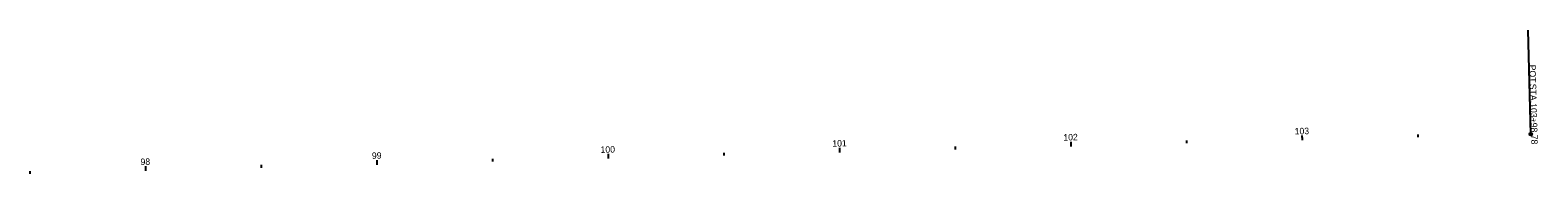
# Model space of a CAD drawing. Extents: x 2402033 to 2407435, y 498456 to 498900.
# Drawn here: x 2406783 to 2407435, y 498766 to 498828 of the extents above; entities that cross this region are included whole.
import ezdxf

# ---------------------------------------------------------------- set-up
doc = ezdxf.new("R2010")
doc.units = 0
for name, color, linetype in [('DR_P_Ditch', 7, 'Continuous'), ('DV_X_Property_Line', 7, 'Continuous'), ('RW_P_Esmt_CH', 7, 'Continuous'), ('RW_P_Esmt_SH', 7, 'Continuous'), ('RW_X_Esmt_SH', 7, 'Continuous'), ('RW_X_Parent_Tract_Area', 7, 'Continuous')]:
    doc.layers.add(name, color=color, linetype=linetype)

msp = doc.modelspace()

# ---------------------------------------------------------------- linework, layer by layer
at = {"layer": 'DR_P_Ditch'}
msp.add_line((2407033.06, 498772.48), (2407033.01, 498774.48), dxfattribs=at)
at = {"layer": 'DV_X_Property_Line'}
msp.add_line((2407431.7, 498783.04), (2407430.51, 498828.02), dxfattribs=at)
msp.add_circle((2407431.7, 498783.04), 0.6, dxfattribs=at)
at = {"layer": 'RW_P_Esmt_CH'}
for p, q in [((2407232.99, 498777.77), (2407232.96, 498778.97)), ((2407332.96, 498780.42), (2407332.92, 498781.62)), ((2407033.06, 498772.48), (2407033.01, 498774.48)), ((2407133.03, 498775.13), (2407132.99, 498776.33)), ((2406833.13, 498767.19), (2406833.1, 498768.39)), ((2406933.1, 498769.83), (2406933.06, 498771.03))]:
    msp.add_line(p, q, dxfattribs=at)
at = {"layer": 'RW_P_Esmt_SH'}
msp.add_line((2407431.7, 498783.04), (2407430.51, 498828.02), dxfattribs=at)
msp.add_circle((2407431.7, 498783.04), 0.6, dxfattribs=at)
at = {"layer": 'RW_X_Esmt_SH'}
for p, q in [((2407232.99, 498777.77), (2407232.94, 498779.77)), ((2407282.97, 498779.1), (2407282.94, 498780.3)), ((2407332.96, 498780.42), (2407332.9, 498782.42)), ((2407382.94, 498781.74), (2407382.91, 498782.94)), ((2406933.1, 498769.83), (2406933.04, 498771.83)), ((2406983.08, 498771.16), (2406983.05, 498772.36)), ((2407033.06, 498772.48), (2407033.01, 498774.48)), ((2407083.04, 498773.8), (2407083.01, 498775)), ((2407133.03, 498775.13), (2407132.97, 498777.13)), ((2407183.01, 498776.45), (2407182.98, 498777.65)), ((2406783.15, 498765.86), (2406783.12, 498767.06)), ((2406833.13, 498767.19), (2406833.08, 498769.19)), ((2406883.11, 498768.51), (2406883.08, 498769.71))]:
    msp.add_line(p, q, dxfattribs=at)
at = {"layer": 'RW_X_Parent_Tract_Area'}
msp.add_line((2407431.7, 498783.04), (2407430.51, 498828.02), dxfattribs=at)
msp.add_circle((2407431.7, 498783.04), 0.6, dxfattribs=at)

# ---------------------------------------------------------------- texts
at = {"layer": 'DR_P_Ditch'}
msp.add_text('100', height=2.8, rotation=1.5166, dxfattribs=at).set_placement((2407029.65, 498774.93))
at = {"layer": 'DV_X_Property_Line'}
for s, p in [('POT', (2407430.94, 498813.03)), (' STA. ', (2407431.14, 498805.83)), ('103+98.78', (2407431.39, 498796.38))]:
    msp.add_text(s, height=2.8, rotation=271.5166, dxfattribs=at).set_placement(p)
at = {"layer": 'RW_P_Esmt_CH'}
msp.add_text('100', height=2.8, rotation=1.5166, dxfattribs=at).set_placement((2407029.65, 498774.93))
at = {"layer": 'RW_P_Esmt_SH'}
for s, p in [('POT', (2407430.94, 498813.03)), (' STA. ', (2407431.14, 498805.83)), ('103+98.78', (2407431.39, 498796.38))]:
    msp.add_text(s, height=2.8, rotation=271.5166, dxfattribs=at).set_placement(p)
at = {"layer": 'RW_X_Esmt_SH'}
for s, p in [('103', (2407329.62, 498782.88)), ('100', (2407029.65, 498774.93)), ('101', (2407129.81, 498777.59)), ('102', (2407229.65, 498780.23)), ('98', (2406830.85, 498769.67)), ('99', (2406930.83, 498772.32))]:
    msp.add_text(s, height=2.8, rotation=1.5166, dxfattribs=at).set_placement(p)
at = {"layer": 'RW_X_Parent_Tract_Area'}
for s, p in [('POT', (2407430.94, 498813.03)), (' STA. ', (2407431.14, 498805.83)), ('103+98.78', (2407431.39, 498796.38))]:
    msp.add_text(s, height=2.8, rotation=271.5166, dxfattribs=at).set_placement(p)

doc.saveas('drawing.dxf')
